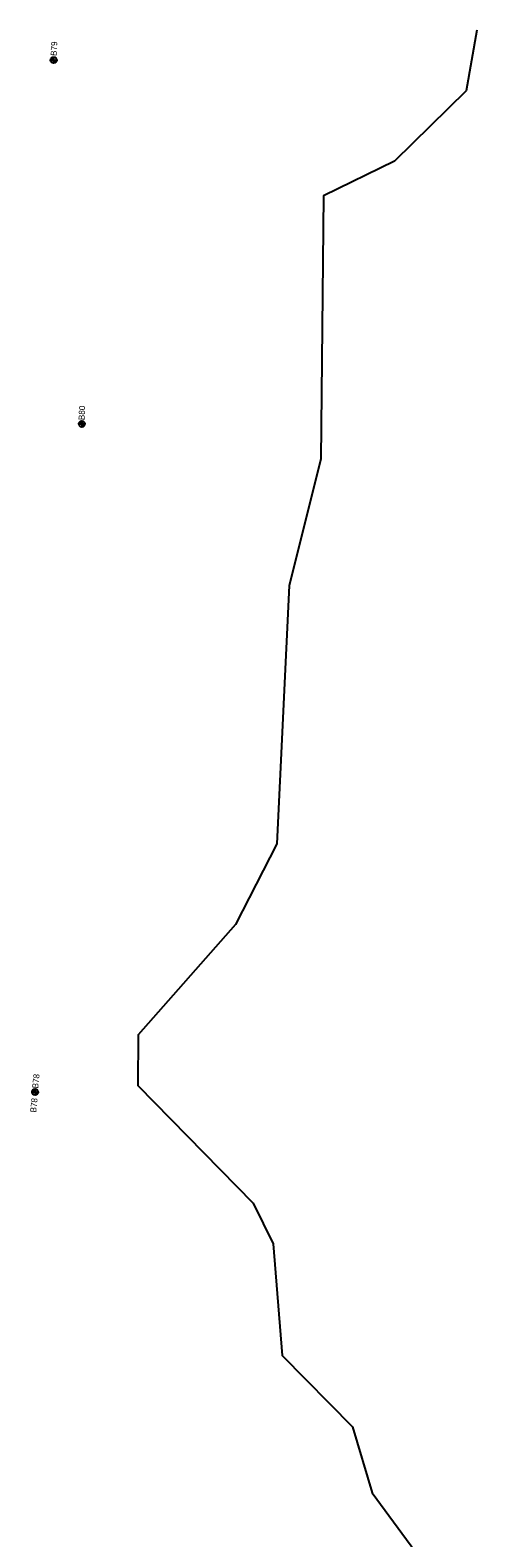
# Model space of a CAD drawing. Extents: x 331323 to 388339, y 121519 to 205315.
# Drawn here: x 360044 to 360779, y 172303 to 174784 of the extents above; entities that cross this region are included whole.
import ezdxf

# ---------------------------------------------------------------- set-up
doc = ezdxf.new("R2010")
doc.units = 0
for name, color, linetype in [('E_SOIL_BORE1 [KAPUR_CADDS_LEVELS]', 7, 'Continuous'), ('E_SOIL_BORE2 [KAPUR_CADDS_LEVELS]', 7, 'Continuous'), ('Level 57', 7, 'Continuous'), ('P_MARK', 7, 'Continuous')]:
    doc.layers.add(name, color=color, linetype=linetype)

msp = doc.modelspace()

# ---------------------------------------------------------------- linework, layer by layer
at = {"layer": 'Level 57'}
msp.add_lwpolyline([(360779.2, 174784), (360761.6, 174684.1), (360643.7, 174568.5), (360526.5, 174511.3), (360522.5, 174078), (360470.5, 173870.1), (360449.9, 173445.3), (360382, 173312.5), (360221.8, 173130.7), (360221, 173047.3), (360411.1, 172853.9), (360443.8, 172787), (360458.8, 172603.5), (360574.5, 172485.8), (360606.8, 172377.1), (360755.1, 172175.8)], dxfattribs=at)
at = {"layer": 'P_MARK'}
for p, q in [((360077.6, 174734.7), (360087.6, 174734.7)), ((360082.6, 174739.7), (360082.6, 174729.7)), ((360124, 174136), (360134, 174136)), ((360129, 174141), (360129, 174131)), ((360047.1, 173036.8), (360057.1, 173036.8)), ((360052.1, 173041.8), (360052.1, 173031.8))]:
    msp.add_line(p, q, dxfattribs=at)
for centre in [(360082.6, 174734.7), (360129, 174136), (360052.1, 173036.8)]:
    msp.add_circle(centre, 5, dxfattribs=at)
for centre, radius, start, end in [((360082.6, 174734.7), 4.5, 89.9869, 179.9869), ((360082.6, 174734.7), 4, 89.9869, 179.9869), ((360082.6, 174734.7), 3.5, 89.9869, 179.9869), ((360082.6, 174734.7), 3, 89.9869, 179.9869), ((360082.6, 174734.7), 2.5, 89.9869, 179.9869), ((360082.6, 174734.7), 2, 89.9869, 179.9869), ((360082.6, 174734.7), 1.5, 89.9869, 179.9869), ((360082.6, 174734.7), 1, 89.9869, 179.9869), ((360082.6, 174734.7), 0.5, 89.9869, 179.9869), ((360082.6, 174734.7), 4.5, 269.9869, 359.9869), ((360082.6, 174734.7), 4, 269.9869, 359.9869), ((360082.6, 174734.7), 3.5, 269.9869, 359.9869), ((360082.6, 174734.7), 3, 269.9869, 359.9869), ((360082.6, 174734.7), 2.5, 269.9869, 359.9869), ((360082.6, 174734.7), 2, 269.9869, 359.9869), ((360082.6, 174734.7), 1.5, 269.9869, 359.9869), ((360082.6, 174734.7), 1, 269.9869, 359.9869), ((360082.6, 174734.7), 0.5, 269.9869, 359.9869), ((360129, 174136), 4.5, 89.9869, 179.9869), ((360129, 174136), 4, 89.9869, 179.9869), ((360129, 174136), 3.5, 89.9869, 179.9869), ((360129, 174136), 3, 89.9869, 179.9869), ((360129, 174136), 2.5, 89.9869, 179.9869), ((360129, 174136), 2, 89.9869, 179.9869), ((360129, 174136), 1.5, 89.9869, 179.9869), ((360129, 174136), 1, 89.9869, 179.9869), ((360129, 174136), 0.5, 89.9869, 179.9869), ((360129, 174136), 4.5, 269.9869, 359.9869), ((360129, 174136), 4, 269.9869, 359.9869), ((360129, 174136), 3.5, 269.9869, 359.9869), ((360129, 174136), 3, 269.9869, 359.9869), ((360129, 174136), 2.5, 269.9869, 359.9869), ((360129, 174136), 2, 269.9869, 359.9869), ((360129, 174136), 1.5, 269.9869, 359.9869), ((360129, 174136), 1, 269.9869, 359.9869), ((360129, 174136), 0.5, 269.9869, 359.9869), ((360052.1, 173036.8), 4.5, 89.9869, 179.9869), ((360052.1, 173036.8), 4, 89.9869, 179.9869), ((360052.1, 173036.8), 3.5, 89.9869, 179.9869), ((360052.1, 173036.8), 3, 89.9869, 179.9869), ((360052.1, 173036.8), 2.5, 89.9869, 179.9869), ((360052.1, 173036.8), 2, 89.9869, 179.9869), ((360052.1, 173036.8), 1.5, 89.9869, 179.9869), ((360052.1, 173036.8), 1, 89.9869, 179.9869), ((360052.1, 173036.8), 0.5, 89.9869, 179.9869), ((360052.1, 173036.8), 4.5, 269.9869, 359.9869), ((360052.1, 173036.8), 4, 269.9869, 359.9869), ((360052.1, 173036.8), 3.5, 269.9869, 359.9869), ((360052.1, 173036.8), 3, 269.9869, 359.9869), ((360052.1, 173036.8), 2.5, 269.9869, 359.9869), ((360052.1, 173036.8), 2, 269.9869, 359.9869), ((360052.1, 173036.8), 1.5, 269.9869, 359.9869), ((360052.1, 173036.8), 1, 269.9869, 359.9869), ((360052.1, 173036.8), 0.5, 269.9869, 359.9869)]:
    msp.add_arc(centre, radius, start, end, dxfattribs=at)

# ---------------------------------------------------------------- texts
at = {"layer": 'E_SOIL_BORE1 [KAPUR_CADDS_LEVELS]'}
for s, rotation, p in [('B80', 87.2646, (360133.4, 174142.1)), ('B78', 84.1728, (360057.1, 173042.3))]:
    msp.add_text(s, height=10, rotation=rotation, dxfattribs=at).set_placement(p)
at = {"layer": 'E_SOIL_BORE2 [KAPUR_CADDS_LEVELS]'}
for s, rotation, p in [('B79', 87.2646, (360087.5, 174741.4)), ('B78', 84.1728, (360053.8, 173002.7))]:
    msp.add_text(s, height=10, rotation=rotation, dxfattribs=at).set_placement(p)

doc.saveas('drawing.dxf')
